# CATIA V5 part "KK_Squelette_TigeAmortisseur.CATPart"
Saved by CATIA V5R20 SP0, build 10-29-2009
Part number: Squelette_tige_amortisseur
Bounding box of the stored display mesh (mm): x -200 to 200, y 768 to 1344, z -3072 to -864
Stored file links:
  G:\Khaled_CFAO_2011\ST2M\ST2M_GR2\aboulegue\Khaled\CAD_thinkMOTION\KK_Squelette_TigeAmortisseur.CATPart
  G:\Khaled_CFAO_2011\ST2M\ST2M_GR2\aboulegue\Khaled\CAD_thinkMOTION\KK_Train_Atterrissage.CATProduct
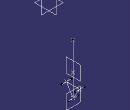
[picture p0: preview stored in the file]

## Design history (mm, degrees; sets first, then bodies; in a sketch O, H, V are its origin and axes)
Set1
  Point1 "Point.14": linked copy from another document
  Point2 to Point4: linked copy from another document
  Plane1 "Plan reference": linked copy from another document
  Point5 "Point.17": linked copy from another document
Set2 "Set squelette tige amortisseur"
  Line1: type PtPt, FirstPoint Point5, SecondPoint Point2
  Line2: type PtPt, FirstPoint Point3, SecondPoint Point4
  Line3: type PtPt, FirstPoint Point3, SecondPoint Point2
  Line4: type PtPt, FirstPoint Point4, SecondPoint Point2
  Line5: type Normal, RefPoint Point3, RefSkin Plane1, Start -200, End 200
  Line6: type Normal, RefPoint Point4, RefSkin Plane1, Start -200, End 200
  Line7: type Normal, RefPoint Point2, RefSkin Plane1, Start -200, End 200
  Plane2 "Plan de reference tige amortisseur": type 2Lines, Element1 Line7, Element2 Line1
  Plane3 "Plan de reference tige amortisseur2": type 2Lines, Element1 Line1, Element2 Line2
Body1 (main body)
